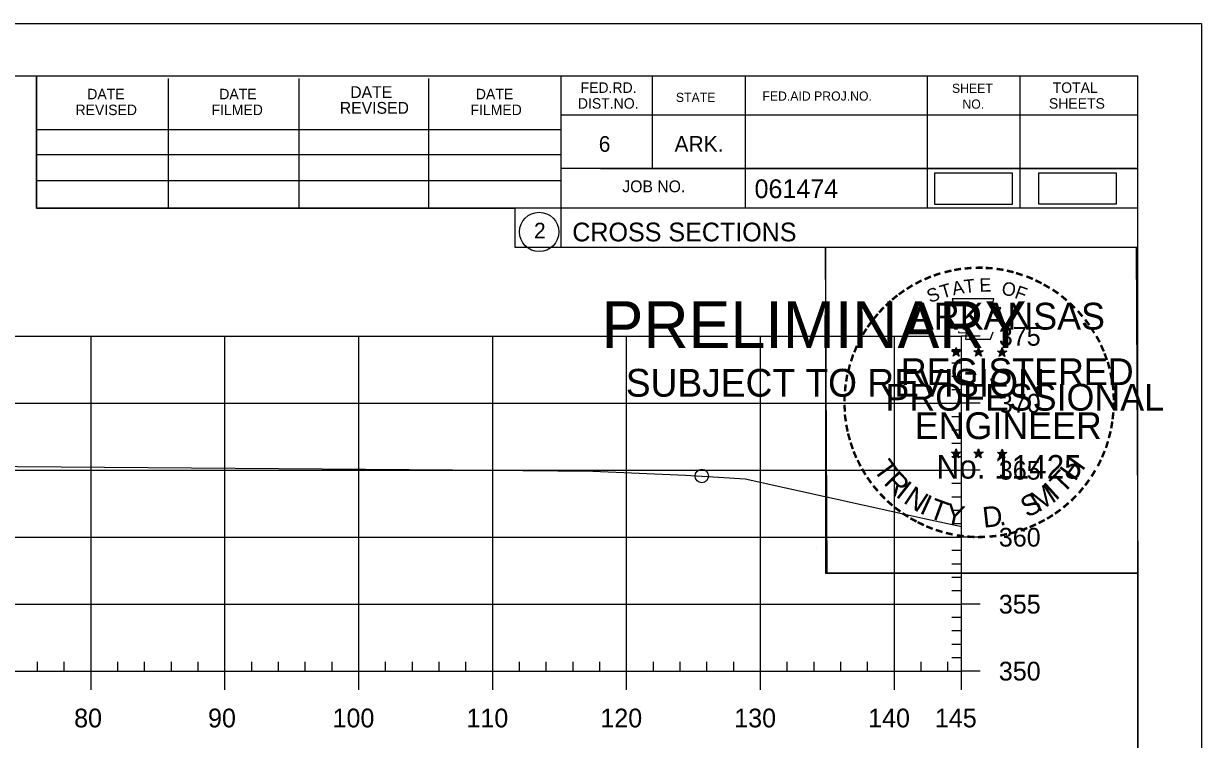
# Model space of a CAD drawing. Extents: x 1359801 to 1362404, y 372415 to 374228.
# Drawn here: x 1361894.9 to 1361982.8, y 373321.2 to 373374.6 of the extents above; entities that cross this region are included whole.
import ezdxf

# ---------------------------------------------------------------- set-up
doc = ezdxf.new("R2010")
doc.units = 0
for name, color, linetype in [('S_DRG_PT_SYM', 7, 'Continuous'), ('S_MAILBOX', 7, 'Continuous'), ('S_PRIMARY_CTL', 7, 'Continuous'), ('S_PRIMARY_CTL_ANNOT', 7, 'Continuous'), ('S_SHOULDER', 7, 'Continuous'), ('S_TELEPHONE_UTILITIES', 7, 'Continuous'), ('S_UNDERGROUND_CABLE', 7, 'Continuous'), ('S_UTL_PT_SYM', 7, 'Continuous'), ('S_WATER_UTILITIES', 7, 'Continuous')]:
    doc.layers.add(name, color=color, linetype=linetype)

msp = doc.modelspace()

# ---------------------------------------------------------------- linework, layer by layer
at = {"layer": 'S_DRG_PT_SYM'}
msp.add_lwpolyline([(1361827.044, 373340.869), (1361834.722, 373341.152), (1361835.161, 373341.168), (1361839.296, 373341.199), (1361887.496, 373341.592), (1361891.131, 373341.564), (1361926.895, 373341.292), (1361937.376, 373341.204), (1361944.29, 373340.882), (1361945.508, 373340.83), (1361946.354, 373340.78), (1361948.751, 373340.622), (1361960.676, 373337.988), (1361962.237, 373337.644), (1361964.89, 373337.048)], dxfattribs=at)
at = {"layer": 'S_MAILBOX'}
for p, q in [((1361674.89, 373351.26), (1361964.89, 373351.26)), ((1361899.89, 373326.26), (1361899.89, 373351.26)), ((1361909.89, 373326.26), (1361909.89, 373351.26)), ((1361919.89, 373326.26), (1361919.89, 373351.26)), ((1361929.89, 373326.26), (1361929.89, 373351.26)), ((1361939.89, 373326.26), (1361939.89, 373351.26)), ((1361949.89, 373326.26), (1361949.89, 373351.26)), ((1361959.89, 373326.26), (1361959.89, 373351.26)), ((1361964.89, 373326.26), (1361964.89, 373351.26)), ((1361674.89, 373346.26), (1361964.89, 373346.26)), ((1361674.89, 373341.26), (1361964.89, 373341.26)), ((1361674.89, 373336.26), (1361964.89, 373336.26)), ((1361674.89, 373331.26), (1361964.89, 373331.26)), ((1361674.89, 373326.26), (1361964.89, 373326.26))]:
    msp.add_line(p, q, dxfattribs=at)
at = {"layer": 'S_SHOULDER'}
for p, q in [((1361649.489, 373374.614), (1361982.823, 373374.614)), ((1361954.105, 373335.464), (1361954.105, 373335.464))]:
    msp.add_line(p, q, dxfattribs=at)
for points in [[(1361649.483, 373374.614), (1361982.823, 373374.614), (1361982.823, 373161.277), (1361649.483, 373161.277)], [(1361895.81, 373370.72), (1361895.81, 373360.84), (1361931.542, 373360.84), (1361931.542, 373357.92), (1361954.742, 373357.92), (1361954.742, 373333.587), (1361978.07, 373333.587), (1361978.07, 373165.26), (1361661.89, 373165.26), (1361661.89, 373370.72)], [(1361954.742, 373357.92), (1361977.95, 373357.92), (1361978.07, 373333.587), (1361954.862, 373333.587)]]:
    msp.add_lwpolyline(points, close=True, dxfattribs=at)
msp.add_circle((1361945.508, 373340.83), 0.5, dxfattribs=at)
at = {"layer": 'S_TELEPHONE_UTILITIES'}
for p, q in [((1361964.155, 373350.175), (1361964.504, 373350.064)), ((1361964.155, 373350.175), (1361964.408, 373350.13)), ((1361964.155, 373350.175), (1361964.392, 373350.053)), ((1361964.504, 373350.429), (1361964.463, 373350.177)), ((1361964.504, 373350.064), (1361964.504, 373350.429)), ((1361964.504, 373350.429), (1361964.553, 373350.179)), ((1361964.851, 373350.175), (1361964.504, 373350.064)), ((1361964.851, 373350.175), (1361964.565, 373350.126)), ((1361964.851, 373350.175), (1361964.647, 373350.073)), ((1361965.825, 373350.175), (1361966.174, 373350.064)), ((1361965.825, 373350.175), (1361966.078, 373350.13)), ((1361965.825, 373350.175), (1361966.062, 373350.053)), ((1361966.174, 373350.429), (1361966.133, 373350.177)), ((1361966.174, 373350.064), (1361966.174, 373350.429)), ((1361966.174, 373350.429), (1361966.223, 373350.179)), ((1361966.521, 373350.175), (1361966.174, 373350.064)), ((1361966.521, 373350.175), (1361966.235, 373350.126)), ((1361966.521, 373350.175), (1361966.317, 373350.073)), ((1361967.589, 373350.163), (1361967.938, 373350.052)), ((1361967.589, 373350.163), (1361967.842, 373350.118)), ((1361967.589, 373350.163), (1361967.826, 373350.041)), ((1361967.938, 373350.417), (1361967.897, 373350.165)), ((1361967.938, 373350.052), (1361967.938, 373350.417)), ((1361967.938, 373350.417), (1361967.987, 373350.167)), ((1361968.285, 373350.163), (1361967.938, 373350.052)), ((1361968.285, 373350.163), (1361967.999, 373350.114)), ((1361968.285, 373350.163), (1361968.081, 373350.061)), ((1361964.288, 373349.767), (1361964.504, 373350.064)), ((1361964.288, 373349.767), (1361964.414, 373350.011)), ((1361964.288, 373349.767), (1361964.502, 373349.984)), ((1361964.717, 373349.767), (1361964.502, 373349.981)), ((1361964.717, 373349.767), (1361964.504, 373350.064)), ((1361964.717, 373349.767), (1361964.58, 373350.058)), ((1361965.958, 373349.767), (1361966.174, 373350.064)), ((1361965.958, 373349.767), (1361966.084, 373350.011)), ((1361965.958, 373349.767), (1361966.172, 373349.984)), ((1361966.387, 373349.767), (1361966.172, 373349.981)), ((1361966.387, 373349.767), (1361966.174, 373350.064)), ((1361966.387, 373349.767), (1361966.25, 373350.058)), ((1361967.722, 373349.755), (1361967.938, 373350.052)), ((1361967.722, 373349.755), (1361967.848, 373349.999)), ((1361967.722, 373349.755), (1361967.936, 373349.972)), ((1361968.151, 373349.755), (1361967.936, 373349.969)), ((1361968.151, 373349.755), (1361967.938, 373350.052)), ((1361968.151, 373349.755), (1361968.014, 373350.046)), ((1361964.151, 373342.602), (1361964.5, 373342.491)), ((1361964.151, 373342.602), (1361964.404, 373342.557)), ((1361964.151, 373342.602), (1361964.388, 373342.48)), ((1361964.284, 373342.194), (1361964.5, 373342.491)), ((1361964.284, 373342.194), (1361964.41, 373342.438)), ((1361964.284, 373342.194), (1361964.498, 373342.411)), ((1361964.5, 373342.856), (1361964.459, 373342.604)), ((1361964.713, 373342.194), (1361964.498, 373342.408)), ((1361964.5, 373342.491), (1361964.5, 373342.856)), ((1361964.5, 373342.856), (1361964.549, 373342.606)), ((1361964.847, 373342.602), (1361964.5, 373342.491)), ((1361964.713, 373342.194), (1361964.5, 373342.491)), ((1361964.847, 373342.602), (1361964.561, 373342.553)), ((1361964.713, 373342.194), (1361964.576, 373342.485)), ((1361964.847, 373342.602), (1361964.643, 373342.5)), ((1361965.82, 373342.602), (1361966.169, 373342.491)), ((1361965.82, 373342.602), (1361966.073, 373342.557)), ((1361965.82, 373342.602), (1361966.057, 373342.48)), ((1361965.953, 373342.194), (1361966.169, 373342.491)), ((1361965.953, 373342.194), (1361966.079, 373342.438)), ((1361965.953, 373342.194), (1361966.167, 373342.411)), ((1361966.169, 373342.856), (1361966.128, 373342.604)), ((1361966.382, 373342.194), (1361966.167, 373342.408)), ((1361966.169, 373342.491), (1361966.169, 373342.856)), ((1361966.169, 373342.856), (1361966.218, 373342.606)), ((1361966.516, 373342.602), (1361966.169, 373342.491)), ((1361966.382, 373342.194), (1361966.169, 373342.491)), ((1361966.516, 373342.602), (1361966.23, 373342.553)), ((1361966.382, 373342.194), (1361966.245, 373342.485)), ((1361966.516, 373342.602), (1361966.312, 373342.5)), ((1361967.587, 373342.592), (1361967.936, 373342.481)), ((1361967.587, 373342.592), (1361967.84, 373342.547)), ((1361967.587, 373342.592), (1361967.824, 373342.47)), ((1361967.72, 373342.184), (1361967.936, 373342.481)), ((1361967.72, 373342.184), (1361967.846, 373342.428)), ((1361967.72, 373342.184), (1361967.934, 373342.401)), ((1361967.936, 373342.846), (1361967.895, 373342.594)), ((1361968.149, 373342.184), (1361967.934, 373342.398)), ((1361967.936, 373342.481), (1361967.936, 373342.846)), ((1361967.936, 373342.846), (1361967.985, 373342.596)), ((1361968.283, 373342.592), (1361967.936, 373342.481)), ((1361968.149, 373342.184), (1361967.936, 373342.481)), ((1361968.283, 373342.592), (1361967.997, 373342.543)), ((1361968.149, 373342.184), (1361968.012, 373342.475)), ((1361968.283, 373342.592), (1361968.079, 373342.49))]:
    msp.add_line(p, q, dxfattribs=at)
for points in [[(1361964.196, 373354.053), (1361964.465, 373353.226)], [(1361967.707, 373353.131), (1361967.849, 373353.415), (1361967.164, 373353.391), (1361967.312, 373354.053), (1361964.196, 373354.053)], [(1361964.688, 373351.63), (1361964.688, 373351.543), (1361965.251, 373351.524), (1361965.197, 373351.051), (1361967.067, 373351.051), (1361967.268, 373351.587)], [(1361964.504, 373350.429), (1361964.717, 373349.767), (1361964.155, 373350.175), (1361964.851, 373350.175), (1361964.288, 373349.767), (1361964.504, 373350.429)], [(1361966.174, 373350.429), (1361966.387, 373349.767), (1361965.825, 373350.175), (1361966.521, 373350.175), (1361965.958, 373349.767), (1361966.174, 373350.429)], [(1361967.938, 373350.417), (1361968.151, 373349.755), (1361967.589, 373350.163), (1361968.285, 373350.163), (1361967.722, 373349.755), (1361967.938, 373350.417)], [(1361964.5, 373342.856), (1361964.713, 373342.194), (1361964.151, 373342.602), (1361964.847, 373342.602), (1361964.284, 373342.194), (1361964.5, 373342.856)], [(1361966.169, 373342.856), (1361966.382, 373342.194), (1361965.82, 373342.602), (1361966.516, 373342.602), (1361965.953, 373342.194), (1361966.169, 373342.856)], [(1361967.936, 373342.846), (1361968.149, 373342.184), (1361967.587, 373342.592), (1361968.283, 373342.592), (1361967.72, 373342.184), (1361967.936, 373342.846)]]:
    msp.add_lwpolyline(points, dxfattribs=at)
for centre, radius in [((1361964.503, 373350.063), 0.172), ((1361964.503, 373350.063), 0.145), ((1361964.503, 373350.063), 0.116), ((1361964.503, 373350.063), 0.0991), ((1361964.503, 373350.063), 0.0747), ((1361964.503, 373350.063), 0.0495), ((1361964.503, 373350.063), 0.0296), ((1361966.173, 373350.063), 0.172), ((1361966.173, 373350.063), 0.145), ((1361966.173, 373350.063), 0.116), ((1361966.173, 373350.063), 0.0991), ((1361966.173, 373350.063), 0.0747), ((1361966.173, 373350.063), 0.0495), ((1361966.173, 373350.063), 0.0296), ((1361967.937, 373350.051), 0.172), ((1361967.937, 373350.051), 0.145), ((1361967.937, 373350.051), 0.116), ((1361967.937, 373350.051), 0.0991), ((1361967.937, 373350.051), 0.0747), ((1361967.937, 373350.051), 0.0495), ((1361967.937, 373350.051), 0.0296), ((1361964.499, 373342.49), 0.172), ((1361964.499, 373342.49), 0.145), ((1361964.499, 373342.49), 0.116), ((1361964.499, 373342.49), 0.0991), ((1361964.499, 373342.49), 0.0747), ((1361964.499, 373342.49), 0.0495), ((1361964.499, 373342.49), 0.0296), ((1361966.168, 373342.49), 0.172), ((1361966.168, 373342.49), 0.145), ((1361966.168, 373342.49), 0.116), ((1361966.168, 373342.49), 0.0991), ((1361966.168, 373342.49), 0.0747), ((1361966.168, 373342.49), 0.0495), ((1361966.168, 373342.49), 0.0296), ((1361967.935, 373342.48), 0.172), ((1361967.935, 373342.48), 0.145), ((1361967.935, 373342.48), 0.116), ((1361967.935, 373342.48), 0.0991), ((1361967.935, 373342.48), 0.0747), ((1361967.935, 373342.48), 0.0495), ((1361967.935, 373342.48), 0.0296)]:
    msp.add_circle(centre, radius, dxfattribs=at)
at = {"layer": 'S_UNDERGROUND_CABLE'}
for points in [[(1361962.88, 373361.123), (1361968.713, 373361.123), (1361968.713, 373363.433), (1361962.88, 373363.433)], [(1361970.649, 373361.145), (1361976.482, 373361.145), (1361976.482, 373363.455), (1361970.649, 373363.455)]]:
    msp.add_lwpolyline(points, close=True, dxfattribs=at)
at = {"layer": 'S_UTL_PT_SYM'}
for p, q in [((1361661.89, 373370.72), (1361978.07, 373370.72)), ((1361895.81, 373360.84), (1361895.81, 373370.72)), ((1361905.67, 373360.84), (1361905.67, 373370.52)), ((1361915.43, 373360.84), (1361915.43, 373370.52)), ((1361925.11, 373360.84), (1361925.11, 373370.52)), ((1361934.97, 373370.72), (1361934.97, 373357.92)), ((1361941.81, 373370.72), (1361941.81, 373363.78)), ((1361948.75, 373370.72), (1361948.75, 373360.84)), ((1361962.33, 373370.72), (1361962.33, 373360.84)), ((1361969.27, 373370.72), (1361969.27, 373360.84)), ((1361978.07, 373165.26), (1361978.07, 373370.72)), ((1361978.07, 373367.78), (1361934.97, 373367.78)), ((1361978.07, 373367.8), (1361978.07, 373367.8)), ((1361895.81, 373366.7), (1361934.97, 373366.7)), ((1361895.81, 373364.84), (1361934.97, 373364.84)), ((1361978.07, 373363.78), (1361934.97, 373363.78)), ((1361937.93, 373363.78), (1361978.07, 373363.78)), ((1361895.81, 373360.84), (1361895.81, 373362.9)), ((1361895.81, 373362.9), (1361934.97, 373362.9)), ((1361978.07, 373360.84), (1361895.81, 373360.84)), ((1361934.97, 373357.92), (1361978.07, 373357.92))]:
    msp.add_line(p, q, dxfattribs=at)
msp.add_circle((1361933.357, 373359.055), 1.467, dxfattribs=at)
at = {"layer": 'S_WATER_UTILITIES'}
for p, q in [((1361964.89, 373326.26), (1361964.89, 373351.26)), ((1361966.29, 373351.26), (1361964.89, 373351.26)), ((1361964.89, 373350.26), (1361964.19, 373350.26)), ((1361964.89, 373349.26), (1361964.19, 373349.26)), ((1361964.89, 373348.26), (1361964.19, 373348.26)), ((1361964.89, 373347.26), (1361964.19, 373347.26)), ((1361966.29, 373346.26), (1361964.89, 373346.26)), ((1361964.89, 373345.26), (1361964.19, 373345.26)), ((1361964.89, 373344.26), (1361964.19, 373344.26)), ((1361964.89, 373343.26), (1361964.19, 373343.26)), ((1361964.89, 373342.26), (1361964.19, 373342.26)), ((1361966.29, 373341.26), (1361964.89, 373341.26)), ((1361964.89, 373340.26), (1361964.19, 373340.26)), ((1361964.89, 373339.26), (1361964.19, 373339.26)), ((1361964.89, 373338.26), (1361964.19, 373338.26)), ((1361964.89, 373337.26), (1361964.19, 373337.26)), ((1361966.29, 373336.26), (1361964.89, 373336.26)), ((1361964.89, 373335.26), (1361964.19, 373335.26)), ((1361964.89, 373334.26), (1361964.19, 373334.26)), ((1361964.89, 373333.26), (1361964.19, 373333.26)), ((1361964.89, 373332.26), (1361964.19, 373332.26)), ((1361966.29, 373331.26), (1361964.89, 373331.26)), ((1361964.89, 373330.26), (1361964.19, 373330.26)), ((1361964.89, 373329.26), (1361964.19, 373329.26)), ((1361964.89, 373328.26), (1361964.19, 373328.26)), ((1361964.89, 373327.26), (1361964.19, 373327.26)), ((1361895.89, 373326.26), (1361895.89, 373326.96)), ((1361897.89, 373326.26), (1361897.89, 373326.96)), ((1361901.89, 373326.26), (1361901.89, 373326.96)), ((1361903.89, 373326.26), (1361903.89, 373326.96)), ((1361905.89, 373326.26), (1361905.89, 373326.96)), ((1361907.89, 373326.26), (1361907.89, 373326.96)), ((1361911.89, 373326.26), (1361911.89, 373326.96)), ((1361913.89, 373326.26), (1361913.89, 373326.96)), ((1361915.89, 373326.26), (1361915.89, 373326.96)), ((1361917.89, 373326.26), (1361917.89, 373326.96)), ((1361921.89, 373326.26), (1361921.89, 373326.96)), ((1361923.89, 373326.26), (1361923.89, 373326.96)), ((1361925.89, 373326.26), (1361925.89, 373326.96)), ((1361927.89, 373326.26), (1361927.89, 373326.96)), ((1361931.89, 373326.26), (1361931.89, 373326.96)), ((1361933.89, 373326.26), (1361933.89, 373326.96)), ((1361935.89, 373326.26), (1361935.89, 373326.96)), ((1361937.89, 373326.26), (1361937.89, 373326.96)), ((1361941.89, 373326.26), (1361941.89, 373326.96)), ((1361943.89, 373326.26), (1361943.89, 373326.96)), ((1361945.89, 373326.26), (1361945.89, 373326.96)), ((1361947.89, 373326.26), (1361947.89, 373326.96)), ((1361951.89, 373326.26), (1361951.89, 373326.96)), ((1361953.89, 373326.26), (1361953.89, 373326.96)), ((1361955.89, 373326.26), (1361955.89, 373326.96)), ((1361957.89, 373326.26), (1361957.89, 373326.96)), ((1361961.89, 373326.26), (1361961.89, 373326.96)), ((1361963.89, 373326.26), (1361963.89, 373326.96)), ((1361674.89, 373326.26), (1361964.89, 373326.26)), ((1361899.89, 373324.86), (1361899.89, 373326.26)), ((1361909.89, 373324.86), (1361909.89, 373326.26)), ((1361919.89, 373324.86), (1361919.89, 373326.26)), ((1361929.89, 373324.86), (1361929.89, 373326.26)), ((1361939.89, 373324.86), (1361939.89, 373326.26)), ((1361949.89, 373324.86), (1361949.89, 373326.26)), ((1361959.89, 373324.86), (1361959.89, 373326.26)), ((1361964.89, 373324.86), (1361964.89, 373326.26)), ((1361966.29, 373326.26), (1361964.89, 373326.26))]:
    msp.add_line(p, q, dxfattribs=at)

# ---------------------------------------------------------------- texts
at = {"layer": 'S_PRIMARY_CTL'}
for s, p in [('375', (1361967.69, 373350.56)), ('370', (1361967.69, 373345.56)), ('365', (1361967.69, 373340.56)), ('360', (1361967.69, 373335.56)), ('355', (1361967.69, 373330.56)), ('350', (1361967.69, 373325.56)), ('80', (1361898.629, 373322.06)), ('90', (1361908.629, 373322.06)), ('100', (1361917.929, 373322.06)), ('110', (1361927.929, 373322.06)), ('120', (1361937.929, 373322.06)), ('130', (1361947.929, 373322.06)), ('140', (1361957.929, 373322.06)), ('145', (1361962.916, 373322.06))]:
    msp.add_text(s, height=1.4, dxfattribs=at).set_placement(p)
at = {"layer": 'S_PRIMARY_CTL_ANNOT'}
for s, height, p in [('PRELIMINARY', 3.5, (1361938.021, 373350.383)), ('DWB', 0.01, (1361938.768, 373352.232)), ('SUBJECT TO REVISION', 2.07511, (1361939.83, 373346.754))]:
    msp.add_text(s, height=height, rotation=360, dxfattribs=at).set_placement(p)
at = {"layer": 'S_SHOULDER'}
msp.add_text('+', height=0.1, dxfattribs=at).set_placement((1361937.333, 373341.154))
at = {"layer": 'S_TELEPHONE_UTILITIES'}
for s, height, rotation, p in [('-', 1.6, 13.63015, (1361963.694, 373355.421)), ('-', 1.6, 10.21935, (1361964.372, 373355.583)), ('-', 1.6, 5.89682, (1361965.101, 373355.693)), ('-', 1.6, 0.18623, (1361965.873, 373355.765)), ('-', 1.6, 357.74304, (1361966.596, 373355.752)), ('-', 1.6, 352.16172, (1361967.34, 373355.696)), ('-', 1.6, 347.20489, (1361968.059, 373355.582)), ('-', 1.6, 28.79182, (1361961.677, 373354.594)), ('-', 1.6, 24.30721, (1361962.31, 373354.911)), ('-', 1.6, 19.17608, (1361962.944, 373355.18)), ('A', 1, 11.21318, (1361964.291, 373354.313)), ('T', 1, 6.02276, (1361965.14, 373354.479)), ('E', 1, 0.83234, (1361966.245, 373354.589)), ('-', 1.6, 342.3362, (1361968.694, 373355.427)), ('-', 1.6, 337.85509, (1361969.429, 373355.204)), ('-', 1.6, 334.12109, (1361970.06, 373354.933)), ('-', 1.6, 36.23174, (1361960.502, 373353.829)), ('-', 1.6, 34.06357, (1361961.08, 373354.224)), ('S', 1, 21.59401, (1361962.551, 373353.731)), ('T', 1, 16.4036, (1361963.465, 373354.062)), ('O', 1, 350.4515, (1361967.849, 373354.379)), ('F', 1, 340.07066, (1361968.803, 373354.151)), ('-', 1.6, 329.64089, (1361970.639, 373354.65)), ('-', 1.6, 325.86266, (1361971.282, 373354.289)), ('-', 1.6, 42.96224, (1361959.593, 373353.034)), ('-', 1.6, 38.95066, (1361960.026, 373353.451)), ('ARKANSAS', 2, 360, (1361961.049, 373351.765)), ('-', 1.6, 320.52971, (1361971.892, 373353.863)), ('-', 1.6, 315.57859, (1361972.491, 373353.375)), ('-', 1.6, 50.61417, (1361958.742, 373352.07)), ('-', 1.6, 48.42305, (1361959.145, 373352.556)), ('-', 1.6, 309.87973, (1361973.06, 373352.825)), ('-', 1.6, 58.07063, (1361958.004, 373350.976)), ('-', 1.6, 54.23247, (1361958.329, 373351.503)), ('-', 1.6, 306.65218, (1361973.585, 373352.223)), ('-', 1.4, 303.67529, (1361974.071, 373351.655)), ('-', 1.6, 62.87135, (1361957.691, 373350.362)), ('-', 1.6, 299.66835, (1361974.39, 373351.048)), ('-', 1.6, 67.77427, (1361957.432, 373349.751)), ('-', 1.6, 294.66279, (1361974.714, 373350.436)), ('-', 1.6, 72.39447, (1361957.213, 373349.121)), ('REGISTERED', 2, 360, (1361960.371, 373347.616)), ('DWB', 0.01, 360, (1361964.491, 373350.059)), ('DWB', 0.01, 360, (1361966.161, 373350.059)), ('DWB', 0.01, 360, (1361967.925, 373350.048)), ('-', 1.6, 290.57283, (1361974.971, 373349.859)), ('-', 1.6, 285.12326, (1361975.205, 373349.279)), ('-', 1.6, 81.20126, (1361956.884, 373347.694)), ('-', 1.6, 75.46096, (1361957.016, 373348.407)), ('-', 1.6, 280.54934, (1361975.405, 373348.537)), ('-', 1.6, 85.18634, (1361956.808, 373347.003)), ('PROFESSIONAL', 2, 360, (1361959.223, 373345.712)), ('-', 1.6, 276.59616, (1361975.567, 373347.769)), ('-', 1.6, 89.06224, (1361956.783, 373346.302)), ('-', 1.6, 274.33011, (1361975.627, 373347.047)), ('-', 1.6, 94.19588, (1361956.818, 373345.577)), ('-', 1.6, 269.94067, (1361975.661, 373346.415)), ('-', 1.6, 98.94793, (1361956.89, 373344.91)), ('ENGINEER', 2, 360, (1361961.41, 373343.587)), ('-', 1.6, 260.99529, (1361975.571, 373345.095)), ('-', 1.6, 263.5172, (1361975.642, 373345.749)), ('-', 1.6, 101.71495, (1361957.025, 373344.177)), ('-', 1.6, 105.45785, (1361957.187, 373343.582)), ('-', 1.6, 255.7626, (1361975.461, 373344.417)), ('-', 1.6, 109.08742, (1361957.402, 373342.951)), ('-', 1.6, 252.86809, (1361975.28, 373343.697)), ('-', 1.6, 114.06432, (1361957.656, 373342.355)), ('T', 1.54, 306.04056, (1361958.26, 373341.329)), ('No. 11425', 1.757, 360, (1361963.038, 373340.636)), ('DWB', 0.01, 360, (1361964.487, 373342.486)), ('DWB', 0.01, 360, (1361966.156, 373342.486)), ('DWB', 0.01, 360, (1361967.923, 373342.476)), ('H', 1.54, 54.60883, (1361973.38, 373340.364)), ('-', 1.6, 247.88866, (1361975.057, 373343.024)), ('-', 1.6, 115.72885, (1361957.961, 373341.737)), ('-', 1.6, 120.44712, (1361958.318, 373341.151)), ('T', 1.54, 46.64442, (1361972.49, 373339.422)), ('-', 1.6, 239.07125, (1361974.401, 373341.643)), ('-', 1.6, 244.61971, (1361974.795, 373342.395)), ('-', 1.6, 125.89344, (1361958.721, 373340.59)), ('R', 1.54, 314.00497, (1361959.022, 373340.281)), ('I', 1.54, 321.96938, (1361959.923, 373339.349)), ('-', 1.6, 233.84524, (1361973.999, 373340.99)), ('-', 1.6, 130.71812, (1361959.183, 373340.038)), ('-', 1.6, 134.22381, (1361959.7, 373339.493)), ('N', 1.54, 326.50021, (1361960.49, 373338.878)), ('M', 1.54, 32.65632, (1361970.645, 373338.097)), ('I', 1.54, 42.11359, (1361971.929, 373338.944)), ('-', 1.6, 231.25377, (1361973.569, 373340.424)), ('-', 1.6, 138.93382, (1361960.225, 373339.029)), ('I', 1.54, 335.36034, (1361961.698, 373338.092)), ('T', 1.54, 339.89117, (1361962.359, 373337.764)), ('Y', 1.54, 347.85558, (1361963.576, 373337.319)), ('S', 1.54, 26.9312, (1361969.806, 373337.691)), ('-', 1.6, 221.08509, (1361972.568, 373339.351)), ('-', 1.6, 225.76533, (1361973.09, 373339.86)), ('-', 1.6, 144.64634, (1361960.781, 373338.623)), ('-', 1.6, 148.08978, (1361961.342, 373338.252)), ('-', 1.6, 151.57039, (1361961.921, 373337.927)), ('D', 1.54, 6.39691, (1361966.561, 373336.96)), ('-', 1.6, 212.24909, (1361971.485, 373338.492)), ('-', 1.6, 215.73633, (1361972.019, 373338.879)), ('-', 1.6, 154.60019, (1361962.443, 373337.68)), ('-', 1.6, 158.56121, (1361963.067, 373337.426)), ('-', 1.6, 162.79826, (1361963.754, 373337.213)), ('.', 1.54, 13.76417, (1361967.753, 373337.088)), ('-', 1.6, 200.71842, (1361969.684, 373337.554)), ('-', 1.6, 204.25161, (1361970.303, 373337.827)), ('-', 1.6, 207.35684, (1361970.927, 373338.146)), ('-', 1.6, 167.55551, (1361964.469, 373337.049)), ('-', 1.6, 173.11546, (1361965.241, 373336.939)), ('-', 1.6, 176.51827, (1361965.989, 373336.886)), ('-', 1.6, 181.59176, (1361966.733, 373336.905)), ('-', 1.6, 185.81666, (1361967.542, 373336.981)), ('-', 1.6, 191.28576, (1361968.278, 373337.113)), ('-', 1.6, 195.47429, (1361969.007, 373337.312))]:
    msp.add_text(s, height=height, rotation=rotation, dxfattribs=at).set_placement(p)
at = {"layer": 'S_UTL_PT_SYM'}
for s, height, p in [('DATE', 0.7819, (1361899.61, 373368.96)), ('DATE', 0.7819, (1361909.47, 373368.96)), ('DATE', 0.8792, (1361919.25, 373369.06)), ('DATE', 0.7819, (1361928.63, 373368.96)), ('FED.RD.', 0.7819, (1361936.45, 373369.44)), ('STATE', 0.684, (1361943.57, 373368.76)), ('FED.AID PROJ.NO.', 0.684, (1361950.03, 373368.86)), ('SHEET', 0.684, (1361964.19, 373369.44)), ('TOTAL', 0.7819, (1361971.71, 373369.44)), ('REVISED', 0.7819, (1361898.73, 373367.78)), ('FILMED', 0.7819, (1361908.89, 373367.78)), ('REVISED', 0.8792, (1361918.47, 373367.88)), ('FILMED', 0.7819, (1361928.23, 373367.78)), ('DIST.NO.', 0.7819, (1361936.25, 373368.26)), ('NO.', 0.684, (1361964.97, 373368.26)), ('SHEETS', 0.7819, (1361971.43, 373368.26)), ('6', 1.172, (1361937.81, 373365.04)), ('ARK.', 1.1723, (1361943.47, 373365.04)), ('JOB NO.', 0.8792, (1361939.57, 373362.02)), ('061474', 1.4, (1361949.446, 373361.579)), ('2', 1.172, (1361932.974, 373358.569)), ('CROSS SECTIONS', 1.4, (1361935.834, 373358.35))]:
    msp.add_text(s, height=height, rotation=360, dxfattribs=at).set_placement(p)

doc.saveas('drawing.dxf')
